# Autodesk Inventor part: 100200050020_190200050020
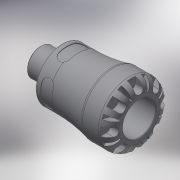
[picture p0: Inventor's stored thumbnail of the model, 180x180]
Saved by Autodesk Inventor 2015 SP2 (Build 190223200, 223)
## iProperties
Created: 2016-12
Part Number: 100200050020_190200050020
Material: Generic
Description: PLASSON MALE ADAPTOR 50X2" SERIES 1
Document SubType Name: Modeling
Designer: KIM
Mass: 447.839 g
Surface Area: 722.341 cm^2
Volume: 447.839 cm^3
Density: 1 g/cm^3
Appearance: Default
Author: KIM
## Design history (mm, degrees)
derived "1002.ipt"
feature "Solid1::1002.ipt"
tag "TaggingFeature1"
body "Solid1"
other parameters: "d0" = 118, "d1" = 34.02, "d3" = 62.5, "d4" = 85, "d6" = 81, "d8" = 72.25, "d13" = 9, "d14" = 9, "d15" = 0, "d17" = 360 deg, "d19" = 8 deg, "d20" = 1, "d21" = 1, "d22" = 8 deg, "d24" = 0, "d26" = 360 deg, "d32" = 0.925, "d33" = 8.5, "d34" = 59.614, "d35" = 6.25, "d38" = 25, "d39" = 1.78842, "d42" = 17.5, "d43" = 11.5, "d45" = 17.64, "d46" = 0, "d59" = 360 deg, "d61" = 14.875, "d62" = 1, "d64" = 0, "d65" = 0.85, "E_" = 85, "H_" = 118, "l_" = 81, "R_" = 59.614, "l_2" = 25, "d9" = 11.25, "d11" = 85, "d12" = 62.5
